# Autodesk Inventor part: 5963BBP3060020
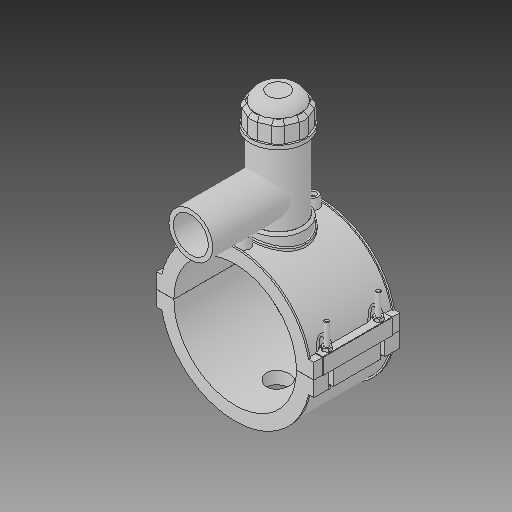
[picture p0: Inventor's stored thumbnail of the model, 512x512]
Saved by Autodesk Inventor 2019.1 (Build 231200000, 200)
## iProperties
Created: 2017-07
Part Number: 5963BBP3060020
Material: Generic
Description: PLASSON TAPPING SADDLE 6''IPS x 2''IPS
Document SubType Name: Modeling
Designer: KIM
Density: 1 g/cm^3
Appearance: Default
Author: KIM
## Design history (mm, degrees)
derived "5963BBP_5963BUP.ipt"
feature "Solid1::5963BBP_5963BUP.ipt"
feature "Solid2::5963BBP_5963BUP.ipt"
feature "Solid3::5963BBP_5963BUP.ipt"
tag "TaggingFeature1"
body "Solid1"
body "Solid2"
body "Solid3"
other parameters: "d0" = 168, "d2" = 215.9, "d3" = 42, "d4" = 118.11, "d5" = 0, "d6" = 0.1, "d8" = 0, "d19" = 6, "d20" = 6, "d21" = 70.866, "d23" = 0, "d24" = 35.433, "d26" = 0, "d27" = 3, "d28" = 3, "d29" = 3, "d30" = 56, "d31" = 6, "d32" = 0, "d33" = 0, "d34" = 0.6, "d40" = 104.832, "d41" = 75.6, "d43" = 0, "d45" = 0, "d47" = 171.666, "d70" = 15, "d72" = 0, "d73" = 6, "d75" = 5, "d76" = 0, "d77" = 8.4, "d78" = 114, "d79" = 15, "d80" = 47.244, "d82" = 5 deg, "d84" = 4, "d85" = 14, "d86" = 0, "d87" = 3, "d88" = 0, "d89" = 1, "d90" = 1, "d91" = 94.488, "d92" = 0, "d93" = 0.5, "d94" = 88.42105, "d96" = 205.632, "d97" = 2.3622, "d98" = 0, "d102" = 1.68, "d120" = 140 deg, "d121" = 24.228, "d122" = 20 deg, "d123" = 403.2, "d124" = 120.96, "d126" = 0, "d143" = 173.04, "d145" = 25.84615, "d149" = 2.52, "d150" = 28.43077, "d153" = 118.11, "d154" = 0, "d156" = 100.8, "d157" = 160 deg, "d159" = 6.72, "d161" = 2.52, "d162" = 70.866, "d163" = 0, "d164" = 84, "d167" = 16.8, "d168" = 98.34146, "d170" = 3.2805, "d172" = 0, "d173" = 1, "d175" = 84, "d176" = 20 deg, "d177" = 11.76, "d178" = 33.6, "d180" = 0, "d183" = 13.44, "d184" = 9.408, "d185" = 38.38575, "d186" = 38.38575, "d187" = 100.8, "d188" = 10.08, "d189" = 11.76, "d190" = 0, "d191" = 151.2, "d193" = 6.9984, "d194" = 4.13385, "d195" = 90 deg, "d197" = 0, "d199" = 0, "d200" = 16.8, "d202" = 0, "d203" = 177.038, "d204" = 71.82, "d205" = 52.92, "d206" = 64.26, "d207" = 132.7785, "d208" = 138.08964, "d209" = 164.64534, "d210" = 65.016, "d211" = 75.6, "d212" = 60.48, "d213" = 31.4766, "d216" = 0, "d217" = 16.8, "d218" = 16.8, "d219" = 3.36, "d222" = 168, "d224" = 0, "d225" = 65.024, "d226" = 60.1, "d227" = 48.08, "d228" = 119.888, "d230" = 5.04, "d_" = 168, "B_" = 215.9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
